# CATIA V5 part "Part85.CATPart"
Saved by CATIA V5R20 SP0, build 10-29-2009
Part number: FA 053000-3
Revision: ANY
Definition: UNKNOWN
Nomenclature: FA 053000-3
Source: Unknown
Bounding box of the stored display mesh (mm): x 0 to 2, y -1.45 to 1.45, z -1.45 to 1.45
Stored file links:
  C:\Users\Utente\Desktop\IO LAVORO\3D X SITO CF\CUMSA\3D files FA\FA 053012-20\Part85.CATPart

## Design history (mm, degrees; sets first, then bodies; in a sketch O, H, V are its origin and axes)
Body1 "Revolución1" (main body)
  Solid1: solid without history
